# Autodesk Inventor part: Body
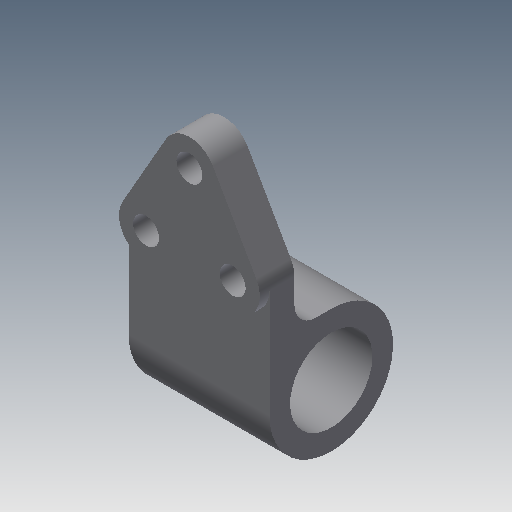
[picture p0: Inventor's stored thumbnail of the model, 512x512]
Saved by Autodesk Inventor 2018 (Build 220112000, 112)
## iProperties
Created: 2010-03
Part Number: Body
Document SubType Name: Modeling
Designer: bhakira
Density: 1 g/cm^3
Material: Generic
Appearance: Default
Author: bhakira
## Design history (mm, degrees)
sketch "Sketch1"
  geometry: L1 (10.853, 41.202)-(30.853, 6.202); L2 (-10.853, 41.202)-(-30.853, 6.202); L3 (-20, -12.5)-(20, -12.5); C1 r 6 at (0, 35); A1 r 12.5 centre (0, 35) between (10.853, 41.202) and (-10.853, 41.202); A2 r 12.5 centre (-20, 0) between (-30.853, 6.202) and (-20, -12.5); A3 r 12.5 centre (20, 0) between (20, -12.5) and (30.853, 6.202); 1 further point
  constraints: 6 end point, 6 point on circle, 6 tangent, 4 centre point, 3 horizontal alignment, 2 equal radius, 1 coincident, 1 vertical alignment, 1 other
  dimensions: "d25" = 35 vertical distance of A1.centre A2.centre; "d27" = 12.5 radius of A1; "d28" = 40 distance of A3.centre A2.centre; "d29" = 20 horizontal distance of A3.centre A1.centre
extrude "Extrusion1" new body sketch "Sketch1" distance "d6" = 16; taper "d7" = 0 deg
workplane "Work Plane2"
workplane "Work Plane3"
sketch "Sketch2"
  geometry: L1 (0, 11.5)-(0, 0); L2 (-12.5, 16)-(6.202, 16) reference; L3 (-50, 11.5)-(0, 11.5); L4 (0, 0)-(-21.5, 0); L5 (-21.5, -17)-(-21.5, 0); L6 (-12.5, 0)-(-12.5, 16) reference; C1 r 19 at (-50, -17); A1 r 28.5 centre (-50, -17) between (-50, 11.5) and (-21.5, -17)
  constraints: 8 end point, 2 centre point, 2 horizontal, 2 point on circle, 2 tangent, 1 coincident, 1 perpendicular, 1 vertical
  dimensions: "d9" = 38 diameter of C1; "d10" = 57 diameter of A1; "d11" = 50 distance from line of L1 C1.centre; "d12" = 33 distance from line of C1.centre L2
extrude "Extrusion2" join sketch "Sketch2" stored distance "d14" = 63.5; taper "d15" = 0 deg
sketch "Sketch3"
  geometry: C1 r 6 at (20, 0) reference; C2 r 6 at (-20, 0) reference; C3 r 6 at (0, 35); 1 further point
  constraints: 1 centre point
extrude "Extrusion3" cut sketch "Sketch3" distance "d16" = 63.5; taper "d17" = 0 deg
node "Sketch4"
hole "Hole1" diameter "d32" = 12; stored, may be unused: countersink angle "d36" = 90 deg, drill point angle "d38" = 118 deg; dims "d33" = 6, "d34" = 4, "d35" = 2082.8, "d37" = 8, "d39" = 10, "d40" = 10
fillet "Fillet1" dims "d42" = 10
body "Solid1"
